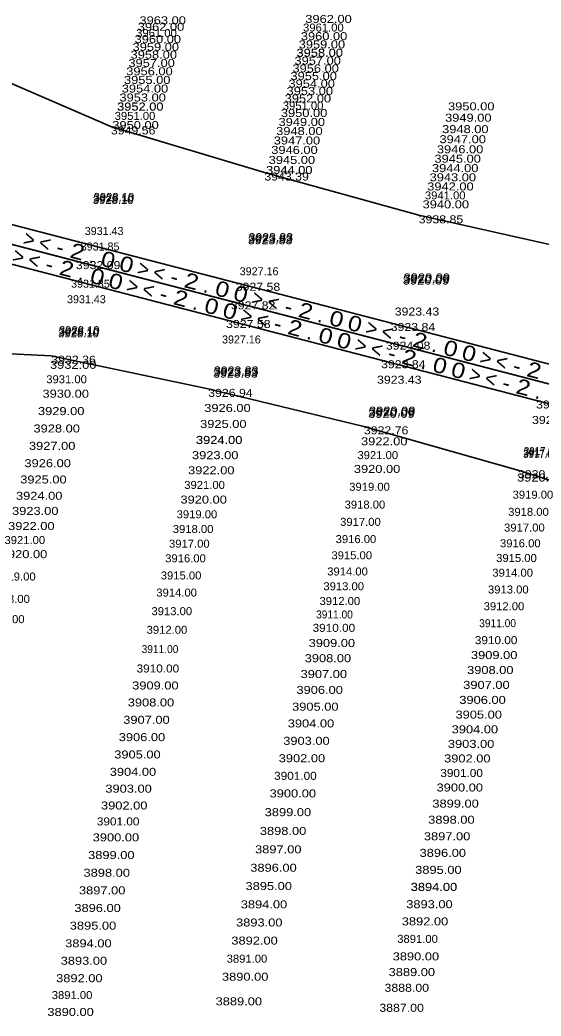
# Model space of a CAD drawing. Extents: x 49942 to 56479, y 47140 to 53283.
# Drawn here: x 54933 to 55258, y 49141 to 49763 of the extents above; entities that cross this region are included whole.
import ezdxf
from ezdxf.enums import TextEntityAlignment as Align

# ---------------------------------------------------------------- set-up
doc = ezdxf.new("R2010")
doc.units = 0
doc.header["$LTSCALE"] = 2
doc.layers.add('29', color=7, linetype='Continuous')
doc.layers.add('59', color=7, linetype='Continuous', lineweight=35)
doc.layers.add('63', color=7, linetype='Continuous', lineweight=35)

msp = doc.modelspace()

# ---------------------------------------------------------------- linework, layer by layer
at = {"layer": '59'}
for p, q in [((54989.852, 49696.838), (54896.947, 49736.929)), ((55085.685, 49668.017), (54989.852, 49696.838)), ((55182.067, 49641.315), (55085.685, 49668.017)), ((55279.721, 49619.507), (55182.067, 49641.315)), ((54952.657, 49553.632), (54850.61, 49558.526)), ((55050.596, 49532.921), (54952.657, 49553.632)), ((55147.836, 49509.522), (55050.596, 49532.921)), ((55244.044, 49482.144), (55147.836, 49509.522)), ((55339.507, 49451.903), (55244.044, 49482.144))]:
    msp.add_line(p, q, dxfattribs=at)
at = {"layer": '63'}
for points in [[(54503.671, 49720.911), (56472.661, 49209.506), (56475.677, 49221.12), (54506.687, 49732.526)], [(54656.01, 49706.141), (56478.694, 49232.735), (56475.677, 49221.12), (54652.993, 49694.526)]]:
    msp.add_lwpolyline(points, close=True, dxfattribs=at)

# ---------------------------------------------------------------- texts
at = {"layer": '29'}
for s, width, p in [('3963.00', 1.2, (55007.706, 49760.577)), ('3962.00', 1.2, (55111.251, 49761.452)), ('3961.00', 1.05, (55005.656, 49752.686)), ('3962.00', 1.2, (55006.661, 49756.555)), ('3961.00', 1.05, (55109.854, 49756.074)), ('3960.00', 1.2, (55004.651, 49748.818)), ('3959.00', 1.2, (55107.122, 49745.554)), ('3960.00', 1.2, (55108.457, 49750.697)), ('3959.00', 1.2, (55003.394, 49743.976)), ('3958.00', 1.2, (55105.75, 49740.272)), ('3958.00', 1.2, (55105.767, 49740.336)), ('3958.00', 1.2, (55105.783, 49740.4)), ('3957.00', 1.2, (55000.789, 49733.947)), ('3958.00', 1.2, (55002.137, 49739.135)), ('3957.00', 1.2, (55104.488, 49735.414)), ('3956.00', 1.2, (54999.442, 49728.759)), ('3956.00', 1.2, (55103.226, 49730.555)), ('3955.00', 1.2, (54998.041, 49723.368)), ('3954.00', 1.2, (55100.763, 49721.073)), ('3955.00', 1.2, (55101.995, 49725.814)), ('3954.00', 1.2, (54996.641, 49717.976)), ('3953.00', 1.2, (55099.564, 49716.454)), ('3953.00', 1.2, (54995.192, 49712.397)), ('3952.00', 1.2, (55098.364, 49711.836)), ('3952.00', 1.2, (54993.701, 49706.657)), ('3952.00', 1.2, (54993.72, 49706.729)), ('3952.00', 1.2, (54993.738, 49706.801)), ('3950.00', 1.2, (55095.997, 49702.721)), ('3951.00', 1.05, (55097.18, 49707.278)), ('3950.00', 1.2, (55200.397, 49706.888)), ('3951.00', 1.05, (54992.21, 49700.916)), ('3949.00', 1.2, (55094.541, 49697.116)), ('3949.00', 1.2, (55198.546, 49699.76)), ('3949.56', 1.15, (54989.852, 49691.838)), ('3950.00', 1.2, (54990.719, 49695.175)), ('3948.00', 1.2, (55093.069, 49691.448)), ('3948.00', 1.2, (55196.694, 49692.632)), ('3947.00', 1.2, (55091.536, 49685.544)), ('3947.00', 1.2, (55195.059, 49686.336)), ('3946.00', 1.2, (55090.002, 49679.641)), ('3946.00', 1.2, (55193.424, 49680.04)), ('3945.00', 1.2, (55088.381, 49673.397)), ('3945.00', 1.2, (55191.897, 49674.161)), ('3944.00', 1.2, (55086.732, 49667.049)), ('3944.00', 1.2, (55086.745, 49667.099)), ('3944.00', 1.2, (55086.757, 49667.148)), ('3944.00', 1.2, (55190.37, 49668.281)), ('3943.39', 1.15, (55085.685, 49663.017)), ('3943.00', 1.2, (55188.885, 49662.563)), ('3942.00', 1.2, (55187.399, 49656.845)), ('3928.10', 1.05, (54978.56, 49648.36)), ('3928.10', 1.05, (54978.811, 49649.328)), ('3928.10', 1.05, (54979.062, 49650.296)), ('3941.00', 1.05, (55185.95, 49651.264)), ('3940.00', 1.2, (55184.5, 49645.682)), ('3938.85', 1.15, (55182.067, 49636.315)), ('3923.83', 1.15, (55075.348, 49623.221)), ('3923.83', 1.15, (55075.6, 49624.189)), ('3923.83', 1.15, (55075.851, 49625.157)), ('3932.09', 1.15, (54968.001, 49607.709)), ('3920.09', 1.2, (55172.137, 49598.082)), ('3920.09', 1.2, (55172.388, 49599.05)), ('3920.09', 1.2, (55172.64, 49600.018)), ('3927.58', 1.15, (55067.807, 49594.184)), ('3927.82', 1.15, (55064.79, 49582.57)), ('3923.43', 1.15, (55167.109, 49578.724)), ('3928.10', 1.05, (54956.94, 49565.122)), ('3928.10', 1.05, (54957.192, 49566.09)), ('3928.10', 1.05, (54957.443, 49567.058)), ('3927.58', 1.15, (55061.773, 49570.955)), ('3923.84', 1.15, (55164.595, 49569.046)), ('3924.08', 1.15, (55161.578, 49557.431)), ('3932.36', 1.15, (54952.657, 49548.632)), ('3932.00', 1.2, (54951.828, 49545.437)), ('3923.83', 1.15, (55053.98, 49540.951)), ('3923.83', 1.15, (55054.232, 49541.919)), ('3923.84', 1.15, (55158.562, 49545.816)), ('3931.00', 1.05, (54949.486, 49536.423)), ('3923.83', 1.15, (55053.729, 49539.983)), ('3923.43', 1.15, (55156.048, 49536.137)), ('3926.94', 1.15, (55050.596, 49527.921)), ('3930.00', 1.2, (54947.145, 49527.409)), ('3929.00', 1.2, (54944.325, 49516.55)), ('3926.00', 1.2, (55048.144, 49518.482)), ('3920.09', 1.2, (55150.769, 49515.812)), ('3920.09', 1.2, (55151.02, 49516.78)), ('3920.76', 1.15, (55255.351, 49520.677)), ('3920.09', 1.2, (55150.517, 49514.844)), ('3920.35', 1.15, (55252.837, 49510.998)), ('3928.00', 1.2, (54941.504, 49505.691)), ('3925.00', 1.2, (55045.558, 49508.522)), ('3922.76', 1.15, (55147.837, 49504.522)), ('3924.00', 1.2, (55042.942, 49498.451)), ('3924.00', 1.2, (55042.957, 49498.509)), ('3924.00', 1.2, (55042.971, 49498.563)), ('3922.00', 1.2, (55146.061, 49497.685)), ('3927.00', 1.2, (54938.688, 49494.85)), ('3917.01', 0.9, (55247.557, 49490.673)), ('3917.01', 0.9, (55247.809, 49491.641)), ('3923.00', 1.2, (55040.491, 49489.015)), ('3921.00', 1.05, (55143.82, 49489.057)), ('3917.01', 0.9, (55247.306, 49489.705)), ('3926.00', 1.2, (54935.873, 49484.008)), ('3922.00', 1.2, (55038.04, 49479.579)), ('3920.00', 1.2, (55141.579, 49480.43)), ('3925.00', 1.2, (54933.23, 49473.834)), ('3920.00', 1.2, (55243.496, 49475.037)), ('3920.26', 1.15, (55244.044, 49477.144)), ('3921.00', 1.05, (55035.664, 49470.43)), ('3919.00', 1.05, (55138.687, 49469.293)), ('3924.00', 1.2, (54930.587, 49463.659)), ('3920.00', 1.2, (55033.288, 49461.281)), ('3919.00', 1.05, (55240.717, 49464.335)), ('3923.00', 1.2, (54928.134, 49454.213)), ('3918.00', 1.05, (55135.794, 49458.156)), ('3918.00', 1.05, (55237.937, 49453.633)), ('3919.00', 1.05, (55030.903, 49452.098)), ('3917.00', 1.05, (55132.995, 49447.381)), ('3922.00', 1.2, (54925.681, 49444.767)), ('3918.00', 1.05, (55028.518, 49442.915)), ('3917.00', 1.05, (55235.385, 49443.807)), ('3921.00', 1.05, (54923.403, 49435.996)), ('3916.00', 1.05, (55130.197, 49436.606)), ('3917.00', 1.05, (55026.139, 49433.756)), ('3916.00', 1.05, (55232.833, 49433.981)), ('3920.00', 1.2, (54921.118, 49427.202)), ('3916.00', 1.05, (55023.76, 49424.598)), ('3915.00', 1.05, (55127.571, 49426.495)), ('3915.00', 1.05, (55230.447, 49424.796)), ('3914.00', 1.05, (55124.945, 49416.385)), ('3919.00', 1.05, (54917.489, 49413.23)), ('3915.00', 1.05, (55020.982, 49413.903)), ('3914.00', 1.05, (55228.061, 49415.61)), ('3913.00', 1.05, (55122.548, 49407.156)), ('3913.00', 1.05, (55225.341, 49405.137)), ('3918.00', 1.05, (54913.861, 49399.259)), ('3914.00', 1.05, (55018.204, 49403.207)), ('3912.00', 1.05, (55120.151, 49397.927)), ('3913.00', 1.05, (55015.187, 49391.592)), ('3912.00', 1.05, (55222.621, 49394.664)), ('3917.00', 1.05, (54910.571, 49386.592)), ('3911.00', 0.95, (55117.977, 49389.559)), ('3912.00', 1.05, (55012.17, 49379.976)), ('3910.00', 1.1, (55115.804, 49381.192)), ('3911.00', 0.95, (55219.872, 49384.08)), ('3910.00', 1.1, (55217.123, 49373.497)), ('3911.00', 0.95, (55009.038, 49367.918)), ('3909.00', 1.2, (55113.341, 49371.709)), ('3908.00', 1.2, (55110.878, 49362.226)), ('3909.00', 1.2, (55214.704, 49364.181)), ('3910.00', 1.1, (55005.892, 49355.804)), ('3908.00', 1.2, (55212.28, 49354.848)), ('3907.00', 1.2, (55108.305, 49352.319)), ('3909.00', 1.2, (55003.136, 49345.192)), ('3906.00', 1.2, (55105.732, 49342.412)), ('3907.00', 1.2, (55209.868, 49345.563)), ('3906.00', 1.2, (55207.432, 49336.184)), ('3908.00', 1.2, (55000.38, 49334.581)), ('3905.00', 1.2, (55103.014, 49331.95)), ('3907.00', 1.2, (54997.567, 49323.753)), ('3905.00', 1.2, (55205.046, 49326.999)), ('3904.00', 1.2, (55100.297, 49321.488)), ('3904.00', 1.2, (55202.661, 49317.813)), ('3906.00', 1.2, (54994.755, 49312.926)), ('3903.00', 1.2, (55097.475, 49310.623)), ('3903.00', 1.2, (55200.298, 49308.715)), ('3905.00', 1.2, (54991.942, 49302.095)), ('3902.00', 1.2, (55094.653, 49299.757)), ('3902.00', 1.2, (55197.935, 49299.618)), ('3904.00', 1.2, (54989.129, 49291.265)), ('3901.00', 1.1, (55091.8, 49288.773)), ('3901.00', 1.1, (55195.578, 49290.546)), ('3903.00', 1.2, (54986.398, 49280.749)), ('3900.00', 1.2, (55193.222, 49281.474)), ('3900.00', 1.2, (55088.947, 49277.789)), ('3902.00', 1.2, (54983.667, 49270.234)), ('3899.00', 1.2, (55190.61, 49271.418)), ('3901.00', 1.1, (54981.082, 49260.281)), ('3899.00', 1.2, (55085.904, 49266.073)), ('3898.00', 1.2, (55187.994, 49261.343)), ('3898.00', 1.2, (55082.861, 49254.357)), ('3900.00', 1.2, (54978.497, 49250.329)), ('3897.00', 1.2, (55185.307, 49250.998)), ('3897.00', 1.2, (55079.875, 49242.86)), ('3899.00', 1.2, (54975.628, 49239.281)), ('3896.00', 1.2, (55182.62, 49240.652)), ('3896.00', 1.2, (55076.889, 49231.363)), ('3895.00', 1.2, (55179.864, 49230.043)), ('3898.00', 1.2, (54972.758, 49228.233)), ('3897.00', 1.2, (54969.901, 49217.233)), ('3895.00', 1.2, (55073.919, 49219.929)), ('3894.00', 1.2, (55177.079, 49219.322)), ('3894.00', 1.2, (55177.094, 49219.377)), ('3894.00', 1.2, (55177.108, 49219.432)), ('3896.00', 1.2, (54967.044, 49206.233)), ('3894.00', 1.2, (55070.949, 49208.494)), ('3893.00', 1.2, (55174.293, 49208.592)), ('3895.00', 1.2, (54964.178, 49195.199)), ('3893.00', 1.2, (55068.01, 49197.177)), ('3892.00', 1.2, (55171.506, 49197.862)), ('3892.00', 1.2, (55065.07, 49185.859)), ('3891.00', 1.05, (55168.667, 49186.932)), ('3894.00', 1.2, (54961.312, 49184.165)), ('3893.00', 1.2, (54958.484, 49173.274)), ('3891.00', 1.05, (55062.14, 49174.578)), ('3890.00', 1.2, (55165.828, 49176.001)), ('3892.00', 1.2, (54955.655, 49162.384)), ('3890.00', 1.2, (55059.21, 49163.297)), ('3889.00', 1.2, (55163.28, 49166.194)), ('3888.00', 1.15, (55160.733, 49156.386)), ('3891.00', 1.05, (54952.916, 49151.839)), ('3889.00', 1.2, (55055.222, 49147.941)), ('3887.00', 1.15, (55157.49, 49143.898)), ('3890.00', 1.2, (54950.178, 49141.295))]:
    msp.add_text(s, height=5, dxfattribs=dict(at, width=width)).set_placement(p)
for s, p in [('3931.43', (54973.532, 49629.002)), ('3931.85', (54971.018, 49619.323)), ('3927.16', (55070.321, 49603.863)), ('3931.85', (54964.985, 49596.094)), ('3931.43', (54962.471, 49586.415)), ('3927.16', (55059.259, 49561.276))]:
    msp.add_text(s, height=5, dxfattribs=at).set_placement(p)
at = {"layer": '63'}
for s, width, p in [('>', 0.95, (54937.757, 49621.804)), ('<', 0.95, (54947.481, 49619.278)), ('-', 1.1, (54957.206, 49616.753)), ('2', 1.2, (54967.799, 49614.001)), ('>', 0.95, (54931.041, 49611.15)), ('<', 0.95, (54940.766, 49608.624)), ('0', 1.2, (54987.005, 49609.013)), ('0', 1.2, (54998.467, 49606.036)), ('-', 1.1, (54950.491, 49606.099)), ('2', 1.2, (54961.084, 49603.347)), ('0', 1.2, (54980.289, 49598.359)), ('>', 0.95, (55009.06, 49603.284)), ('<', 0.95, (55018.785, 49600.759)), ('0', 1.2, (54991.751, 49595.382)), ('>', 0.95, (55002.345, 49592.631)), ('-', 1.1, (55028.509, 49598.233)), ('2', 1.2, (55039.103, 49595.481)), ('<', 0.95, (55012.07, 49590.105)), ('0', 1.2, (55058.308, 49590.493)), ('0', 1.2, (55069.77, 49587.516)), ('-', 1.1, (55021.794, 49587.579)), ('2', 1.2, (55032.387, 49584.828)), ('0', 1.2, (55051.593, 49579.839)), ('>', 0.95, (55080.364, 49584.765)), ('<', 0.95, (55090.088, 49582.239)), ('0', 1.2, (55063.055, 49576.862)), ('>', 0.95, (55073.648, 49574.111)), ('-', 1.1, (55099.813, 49579.713)), ('2', 1.2, (55110.406, 49576.962)), ('<', 0.95, (55083.373, 49571.585)), ('0', 1.2, (55129.612, 49571.974)), ('0', 1.2, (55141.074, 49568.997)), ('-', 1.1, (55093.097, 49569.059)), ('2', 1.2, (55103.691, 49566.308)), ('0', 1.2, (55122.896, 49561.32)), ('>', 0.95, (55151.667, 49566.245)), ('<', 0.95, (55161.392, 49563.719)), ('0', 1.2, (55134.358, 49558.343)), ('>', 0.95, (55144.952, 49555.591)), ('-', 1.1, (55171.116, 49561.194)), ('2', 1.2, (55181.71, 49558.442)), ('<', 0.95, (55154.676, 49553.066)), ('0', 1.2, (55200.915, 49553.454)), ('0', 1.2, (55212.377, 49550.477)), ('-', 1.1, (55164.401, 49550.54)), ('2', 1.2, (55174.994, 49547.788)), ('0', 1.2, (55194.2, 49542.8)), ('>', 0.95, (55222.971, 49547.725)), ('<', 0.95, (55232.695, 49545.2)), ('0', 1.2, (55205.662, 49539.823)), ('>', 0.95, (55216.255, 49537.072)), ('-', 1.1, (55242.42, 49542.674)), ('2', 1.2, (55253.013, 49539.923)), ('<', 0.95, (55225.98, 49534.546)), ('2', 1.2, (55246.298, 49529.269)), ('-', 1.1, (55235.704, 49532.02))]:
    msp.add_text(s, height=9.6, rotation=345.44, dxfattribs=dict(at, width=width)).set_placement(p, align=Align.CENTER)
for p in [(54977.402, 49611.507), (54970.687, 49600.853), (55048.705, 49592.987), (55041.99, 49582.333), (55120.009, 49574.468), (55113.294, 49563.814), (55191.312, 49555.948), (55184.597, 49545.294), (55255.901, 49526.774)]:
    msp.add_text('.', height=9.6, rotation=345.44, dxfattribs=at).set_placement(p, align=Align.CENTER)

doc.saveas('drawing.dxf')
